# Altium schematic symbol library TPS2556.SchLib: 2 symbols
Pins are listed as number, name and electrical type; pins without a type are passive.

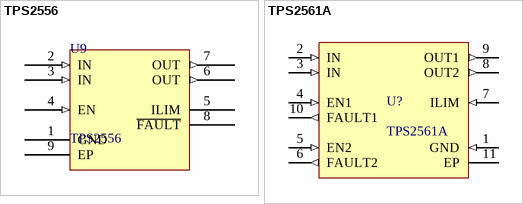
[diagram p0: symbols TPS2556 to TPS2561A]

## TPS2556
designator U9
footprint DRB0008B
pins: 1 GND, 2 IN (in), 3 IN (in), 4 EN (in), 5 ILIM, 6 OUT (out), 7 OUT (out), 8 ~{FAULT}, 9 EP

## TPS2561A
designator U?
footprint DRC0010J
pins: 1 GND (in), 2 IN (in), 3 IN (in), 4 EN1 (in), 5 EN2 (in), 6 FAULT2 (out), 7 ILIM (in), 8 OUT2 (out), 9 OUT1 (out), 10 FAULT1 (out), 11 EP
